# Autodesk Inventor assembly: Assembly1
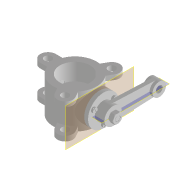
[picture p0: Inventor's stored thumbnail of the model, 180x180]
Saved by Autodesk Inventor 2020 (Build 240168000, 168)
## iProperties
Created: 2019-03
Part Number: Assembly1
Document SubType Name: Assembly
Designer: LENOVO-CADCIM
Author: LENOVO-CADCIM
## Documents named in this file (10)
- D:\Autodesk Inventor_2020\Resources1\c10\c10_Inv_2019_tut\c10_Inv_tut_2019\c10_tut01_inv\Butterfly Valve\Butterfly Valve Assembly.iam
- D:\Autodesk Inventor_2020\Resources1\c10\c10_Inv_2019_tut\c10_Inv_tut_2019\c10_tut01_inv\Butterfly Valve\Body.ipt
- D:\Autodesk Inventor_2020\Resources1\c10\c10_Inv_2019_tut\c10_Inv_tut_2019\c10_tut01_inv\Butterfly Valve\Shaft.ipt
- D:\Autodesk Inventor_2020\Resources1\c10\c10_Inv_2019_tut\c10_Inv_tut_2019\c10_tut01_inv\Butterfly Valve\Retainer.ipt
- D:\Autodesk Inventor_2020\Resources1\c10\c10_Inv_2019_tut\c10_Inv_tut_2019\c10_tut01_inv\Butterfly Valve\Arm1.ipt
- D:\Autodesk Inventor_2020\Resources1\c10\c10_Inv_2019_tut\c10_Inv_tut_2019\c10_tut01_inv\Butterfly Valve\Plate.ipt
- D:\Autodesk Inventor_2020\Resources1\c10\c10_Inv_2019_tut\c10_Inv_tut_2019\c10_tut01_inv\Butterfly Valve\scew1.ipt
- D:\Autodesk Inventor_2020\Resources1\c10\c10_Inv_2019_tut\c10_Inv_tut_2019\c10_tut01_inv\Butterfly Valve\Screw.ipt
- D:\Autodesk Inventor_2020\Resources1\c10\c10_Inv_2019_tut\c10_Inv_tut_2019\c10_tut01_inv\Butterfly Valve\Parallel key.ipt
- D:\Autodesk Inventor_2020\Resources1\c10\c10_Inv_2019_tut\c10_Inv_tut_2019\c10_tut01_inv\Butterfly Valve\Nut.ipt
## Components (12 placed, 9 different names)
1. Body:1 — Insert:1, Insert:2, Mate:1, Angle:2, Angle:3, Angle:4
2. Shaft:1 — Insert:1, Angle:2, Angle:3, Insert:3, Insert:4, Mate:3, Insert:11
3. Retainer:1 — Insert:2, Mate:1, Insert:7, Insert:10
4. Arm1:1 — Insert:10, Mate:2, Flush:1
5. Plate:1 — Insert:3, Insert:4, Insert:5, Insert:6
6. scew1:1 — Insert:5
7. scew1:2 — Insert:6
8. Parallel key:1 — Mate:2, Mate:3, Flush:1
9. Nut:1 — Insert:11, Angle:4
10. Screw:1 — Insert:7
11. Screw:2
12. Screw:3
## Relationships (16: Insert 9, Mate 3, Angle 3, Flush 1)
- Insert:1: Body:1 ↔ Shaft:1
- Insert:2: Body:1 ↔ Retainer:1
- Mate:1: Body:1 ↔ Retainer:1
- Angle:2: Body:1 ↔ Shaft:1
- Angle:3: Body:1 ↔ Shaft:1
- Insert:3: Shaft:1 ↔ Plate:1
- Insert:4: Shaft:1 ↔ Plate:1
- Insert:5: Plate:1 ↔ scew1:1
- Insert:6: Plate:1 ↔ scew1:2
- Insert:7: Retainer:1 ↔ Screw:1
- Insert:10: Retainer:1 ↔ Arm1:1
- Mate:2: Arm1:1 ↔ Parallel key:1
- Mate:3: Shaft:1 ↔ Parallel key:1
- Flush:1: Arm1:1 ↔ Parallel key:1
- Insert:11: Shaft:1 ↔ Nut:1
- Angle:4: Body:1 ↔ Nut:1
